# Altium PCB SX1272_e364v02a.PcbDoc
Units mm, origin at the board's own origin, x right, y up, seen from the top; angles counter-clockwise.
Board outline 65 x 53.3 mm, 4 copper layers (Top Layer, MidLayer1, MidLayer2, Bottom Layer), stack 1.661 mm thick; 73 components, 54 nets, 215 pads, 691 vias.
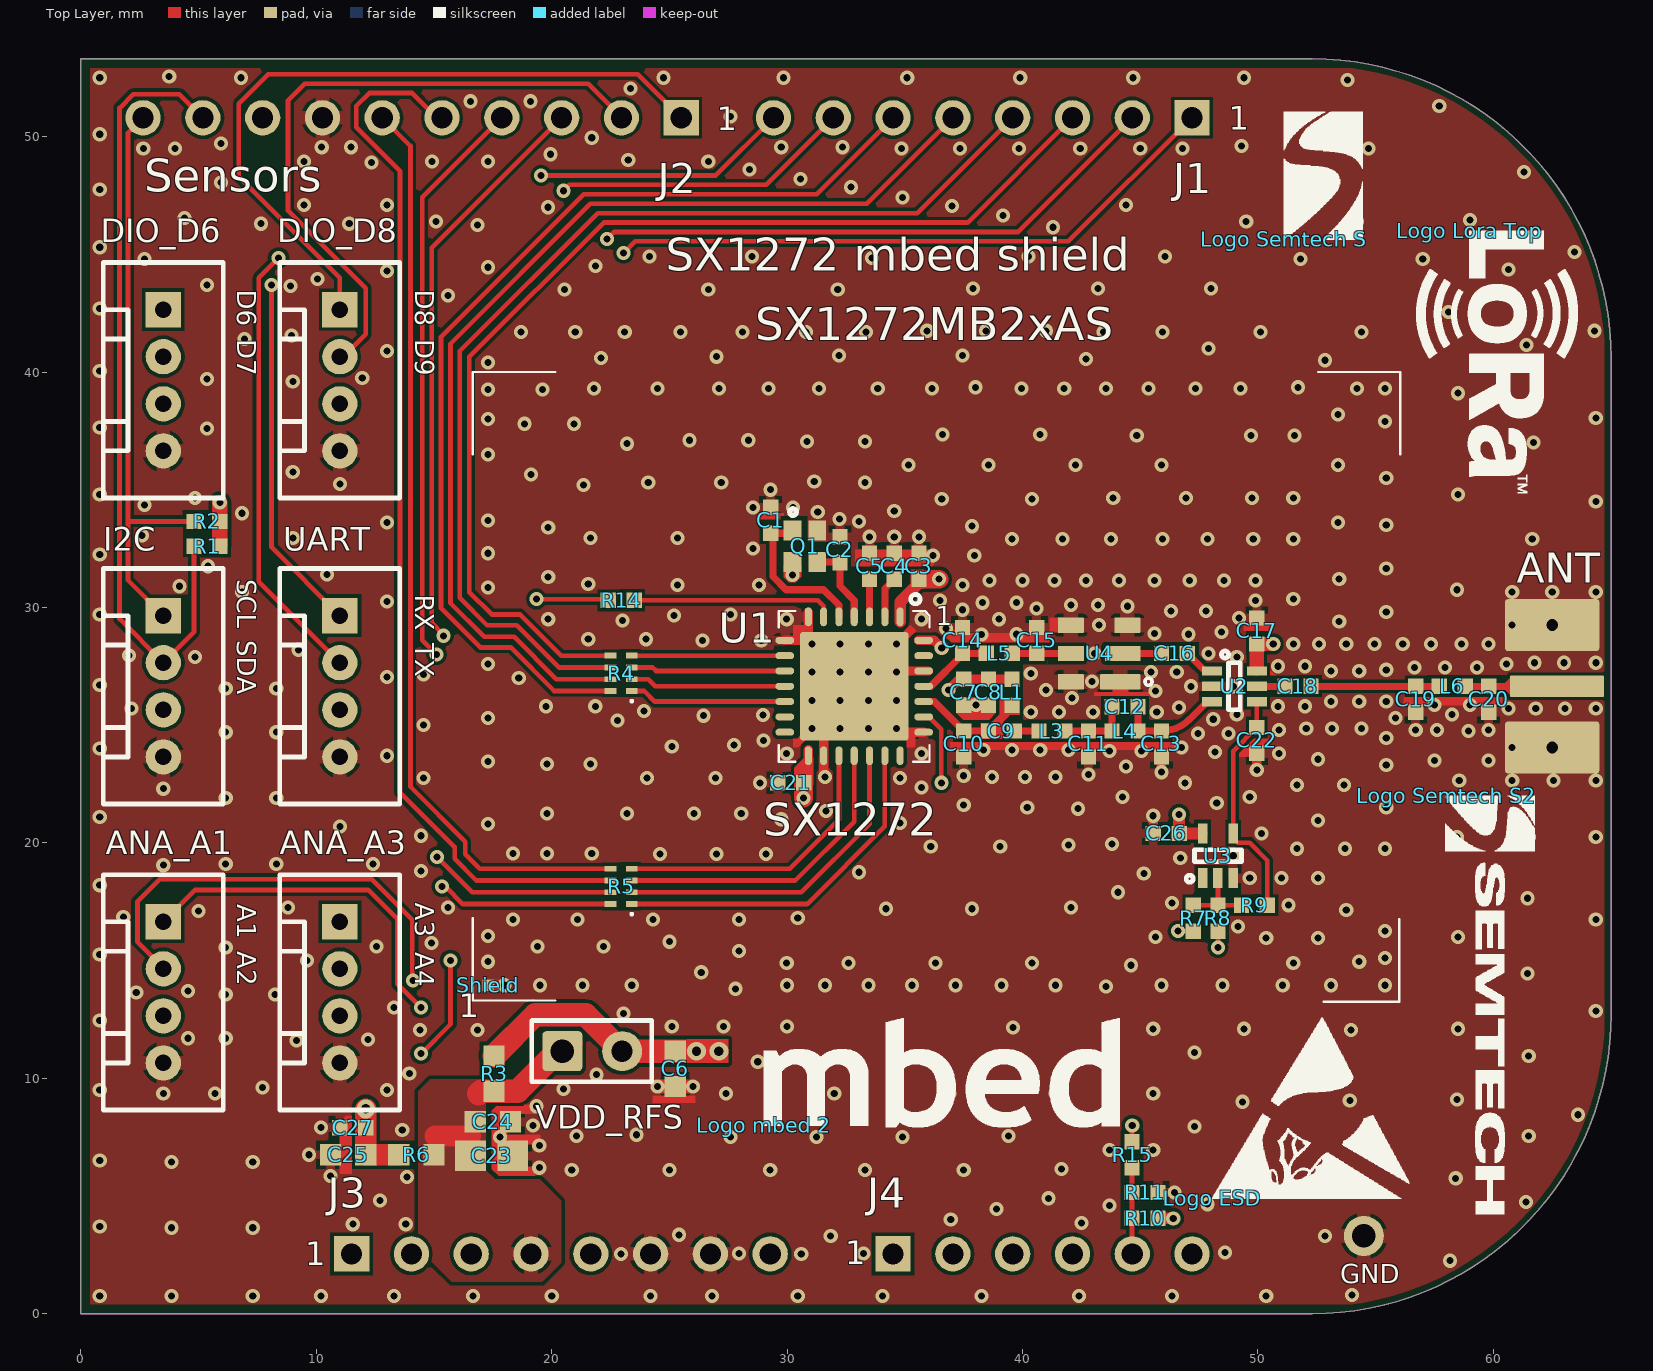
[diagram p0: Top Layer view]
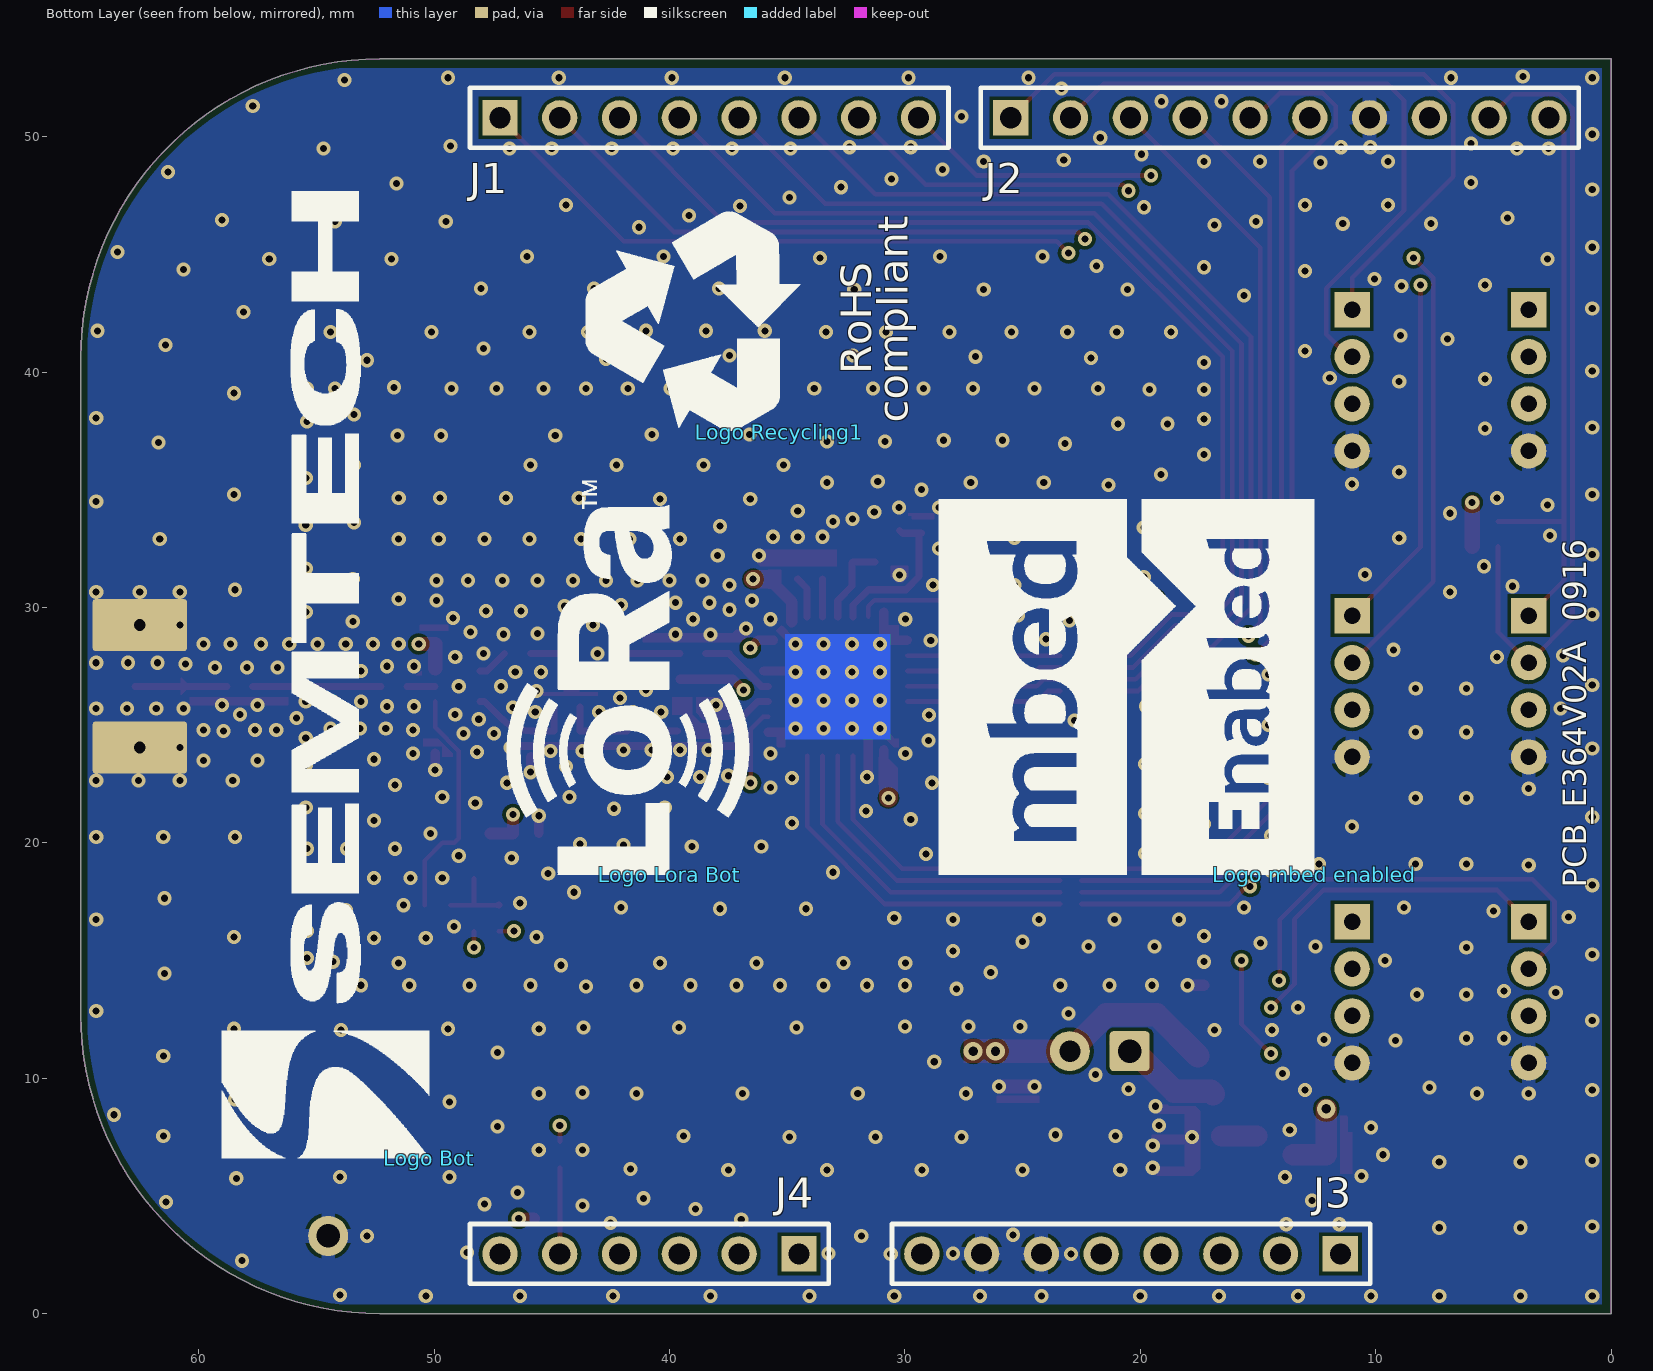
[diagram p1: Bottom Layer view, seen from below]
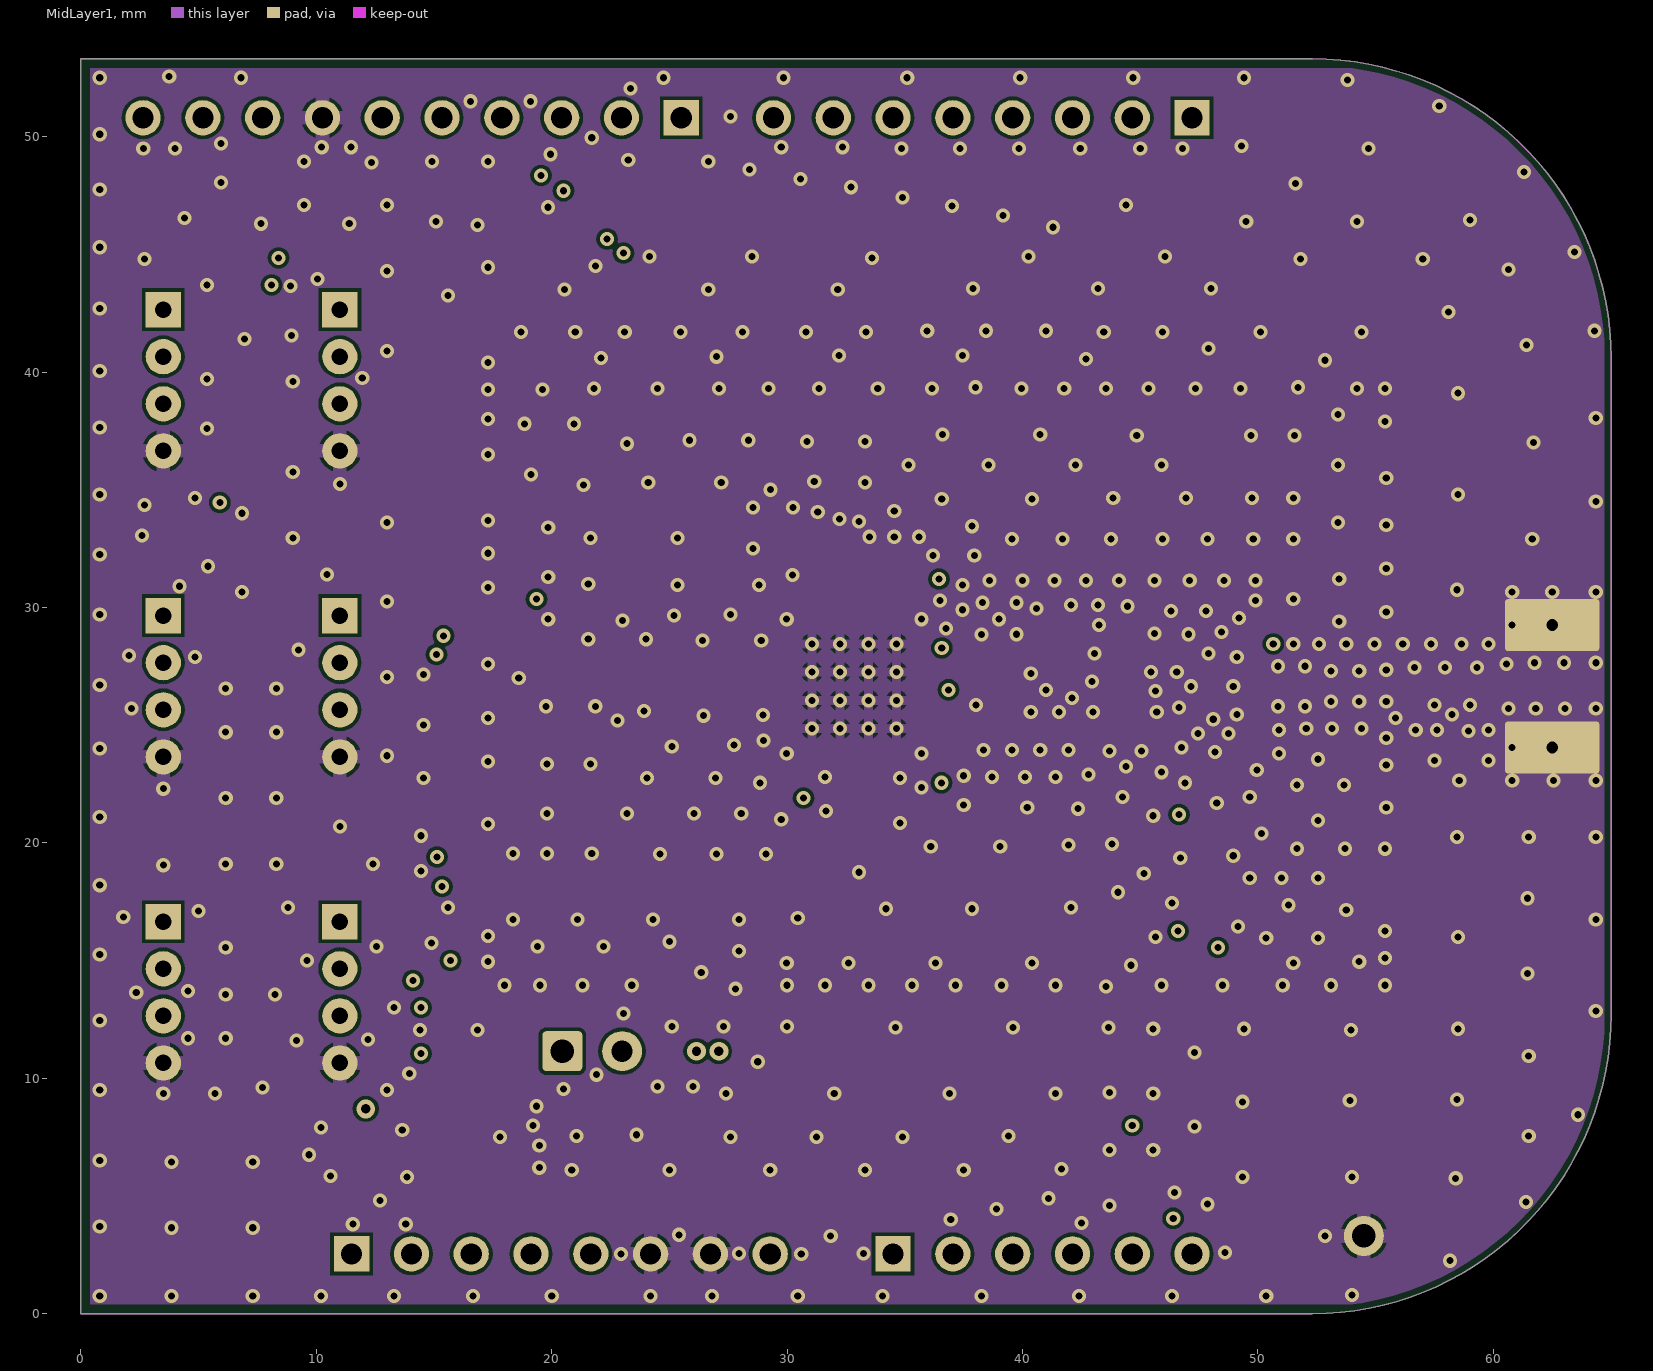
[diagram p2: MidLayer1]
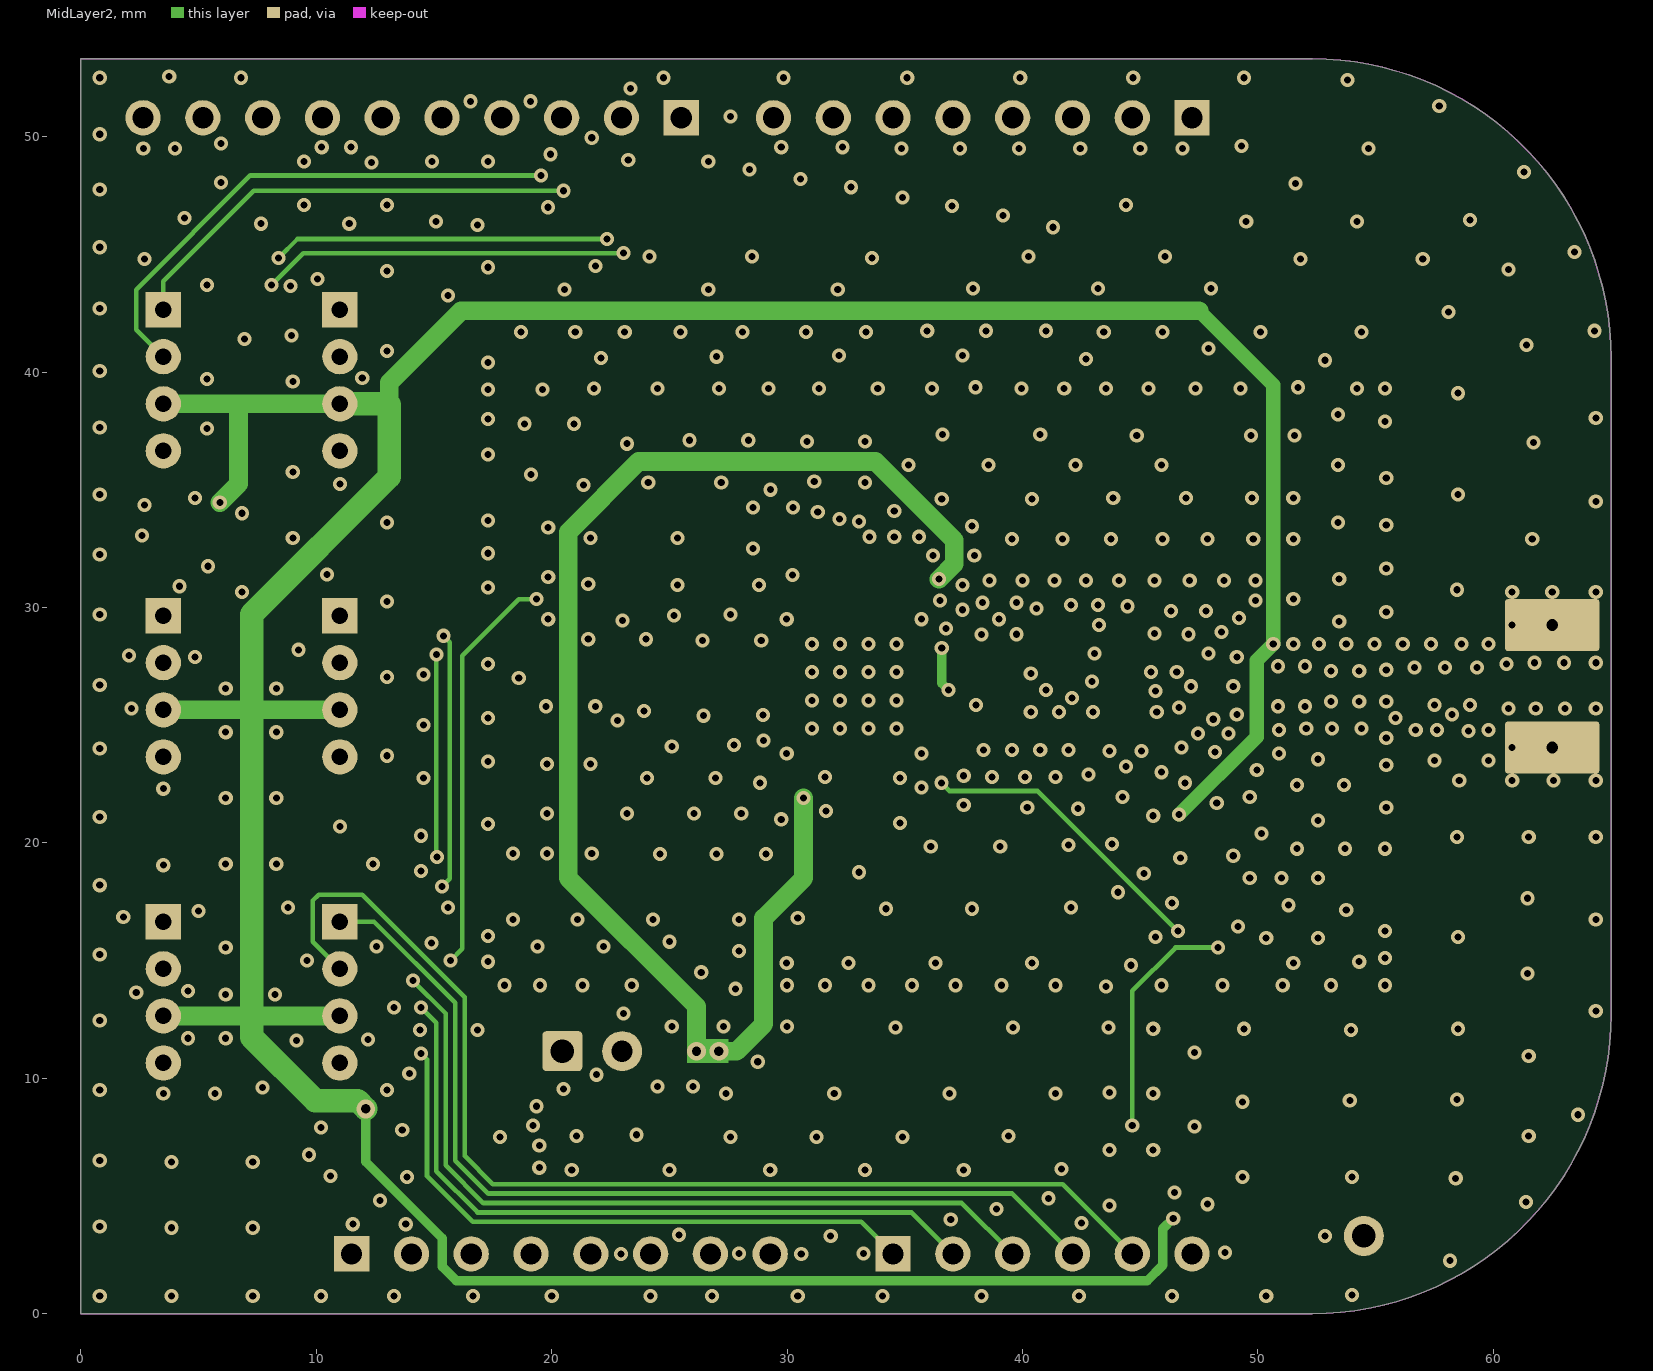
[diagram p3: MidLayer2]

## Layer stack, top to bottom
Top Layer: signal copper 0.035
Dielectric: core 0.2, FR-4, Dk 4.3
MidLayer1: signal copper 0.0356
Dielectric: prepreg 1.12, FR-4, Dk 4.3
MidLayer2: signal copper 0.0356
Dielectric: core 0.2, FR-4, Dk 4.3
Bottom Layer: signal copper 0.035

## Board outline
0,0 52.3,0 ccw(c52.3,12.7) 65,12.7 65,40.6 ccw(c52.3,40.6) 52.3,53.3 0,53.3

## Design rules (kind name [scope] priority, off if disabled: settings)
Clearance Clearance_GND_Keepout [InNet('GND') vs OnLayer('Keep-Out Layer')] p1: gap=0.25
Clearance Clearance_GND [InNet('GND')] p2: gap=0.15
Clearance [All] p3: gap=0.15
ComponentClearance [All] p1: gap=0.25 collisioncheckmode=3 verticalgap=0.3 showdistances=FALSE
HoleSize [All] p1: absolutevalues=TRUE maxlimit=3.6 minlimit=0.25 maxpercent=80.000 minpercent=20.000
HoleToHoleClearance [All] p1: gap=0.2 allowstackedmicrovias=TRUE
MinimumSolderMaskSliver [All] p1: minsoldermaskwidth=0.05
PlaneClearance [All] p1: clearance=0.2
PlaneConnect [All] p1: planeconnectstyle=Direct reliefexpansion=0.508 reliefentries=4 reliefconductorwidth=0.254 reliefairgap=0.254
PolygonConnect "PolygonConnect SAW SMD PACKAGE" [InNet('GND') vs HasFootprint('DCC6C_3.0X3.0MM')] p1: connectstyle=Relief reliefconductorwidth=0.65 reliefentries=4 polygonreliefangle="90 Angle"
PolygonConnect "PolygonConnect SMD" [InNet('GND') vs HasFootprint('vqfn28_6x6mm')  or HasFootprint('nd3225da - nd2520da')  or  HasFootprint('rlc_1206_smd capa pol') or HasFootprint('rlc_603_smd') or HasFootprint('rlc_402_smd') or HasFootprint('rlc_402_smd diode') or hasFootprint('rlc_805_smd') or HasFootprint('rlc_1210_smd')  or HasFootprint('SC70-6') or HasFootprint('SC70-5')] p2: connectstyle=Relief reliefconductorwidth=0.4 reliefentries=4 polygonreliefangle="90 Angle"
PolygonConnect PolygonConnect_comp_diverse [InNet('GND') or  InNet('VDD_RF') vs HasFootprint('CD1608-0603') or  HasFootprint('BRIDGE_254MM') or  HasFootprint('pin_1mm') or HasFootprint('SMA_END_LAUNCH_JACK_RECEPTACLE')   or  HasFootprint('HDR2X8')   or  HasFootprint('HDR2X6')  or  HasFootprint('HDR2X10')   or  HasFootprint('HDR1X10') or  HasFootprint('HDR1X8')  or  HasFootprint('HDR1X6')  or  HasFootprint('1125S-4P_connector')] p3: connectstyle=Relief reliefconductorwidth=0.6 reliefentries=4 polygonreliefangle="90 Angle"
PolygonConnect PolygonConnect_all [All] p4: connectstyle=Direct reliefconductorwidth=0.6 reliefentries=4 polygonreliefangle="90 Angle"
RoomDefinition SX1272_e364v02a [InComponentClass('SX1272_e364v02a')] p1: confinementstyle=ConfineOut formatcopy=TRUE lockcomponents=FALSE outline 94.9,15.9 94.9,42.5 95.1,42.7 139,42.7 139,16
RoutingVias [All] p1: holewidth=0.3 width=0.6 viastyle="Through Hole" minholewidth=0.25 minwidth=0.5 maxholewidth=0.4 maxwidth=0.8
SilkToSilkClearance [All] p1: silktosilkclearance=0.05
SilkscreenOverComponentPads [All] p1: minsilkscreentomaskgap=0.05
SolderMaskExpansion [All] p1: expansion=0.05
Width "Width GND" [InNet('GND')] p1: maxlimit=3 minlimit=0.2 preferedwidth=0.4
Width Width_VCC [InNet('VDD_RF') or  InNet('VDD_RFS') or  InNet('VCC') or  InNet('VBAT') or InNet('VCC_FEM')] p2: maxlimit=2 minlimit=0.2 preferedwidth=0.8
Width "Width All" [All] p3: maxlimit=2 minlimit=0.15 preferedwidth=0.2
20 further rules are at their usual default settings.

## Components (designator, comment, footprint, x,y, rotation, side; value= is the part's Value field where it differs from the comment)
ANA_A1 "Header 4" 1125S-4P_connector 3.5,16.65 r270 top locked
ANA_A3 "Header 4" 1125S-4P_connector 11,16.65 r270 top locked
ANT "SMA" "SMA END LAUNCH JACK RECEPTACLE SHORT" 62.7,26.65 r90 top locked
C1 "Cap" rlc_402_smd 29.3,33.7 r270 top
C2 "Cap" rlc_402_smd 32.245,32.45 r270 top
C3 "Cap" rlc_402_smd 35.6,31.75 r270 top
C4 "Cap" rlc_402_smd 34.55,31.75 r270 top
C5 "Cap" rlc_402_smd 33.5,31.75 r270 top
C6 "Cap" rlc_603_smd 25.25,10.4 r90 top
C7 "Cap" rlc_402_smd 37.5,26.4 r90 top
C8 "Cap" rlc_402_smd 38.55,26.4 r90 top
C9 "Cap" rlc_402_smd 39.1,24.75 r180 top
C10 "Cap" rlc_402_smd 37.5,24.2 r90 top
C11 "Cap" rlc_402_smd 42.8,24.2 r90 top
C12 "Cap" rlc_402_smd 44.35,25.777 r180 top
C13 "Cap" rlc_402_smd 45.9,24.2 r90 top
C14 "Cap" rlc_402_smd 37.45,28.6 r270 top
C15 "Cap" rlc_402_smd 40.6,28.6 r270 top
C16 "Cap" rlc_402_smd 46.45,28.046 r180 top
C17 "Cap" rlc_402_smd 49.95,29 r270 top
C18 "Cap" rlc_402_smd 51.7,26.65 r180 top
C19 "Cap" rlc_402_smd 56.7,26.1 r90 top
C20 "Cap" rlc_402_smd 59.8,26.1 r90 top
C21 "Cap" rlc_402_smd 30.15,22.55 r0 top
C22 "Cap" rlc_402_smd 49.95,24.35 r270 top
C23 "Cap" rlc_805_smd 17.45,6.7 r180 top
C24 "Cap" rlc_603_smd 17.5,8.15 r180 top
C25 "Cap" rlc_603_smd 11.35,6.75 r0 top
C26 "Cap" rlc_402_smd 46.1,20.4 r0 top
C27 "Cap" rlc_402_smd 11.55,7.9 r0 top
DIO_D6 "Header 4" 1125S-4P_connector 3.5,42.65 r270 top locked
DIO_D8 "Header 4" 1125S-4P_connector 11,42.65 r270 top locked
GND "Test Pin" pin_1mm 55,3.8 r0 top
I2C "Header 4" 1125S-4P_connector 3.5,29.65 r270 top locked
J1 "Header 8" HDR1X8 47.2,50.8 r180 bottom locked
J2 "Header 10" HDR1X10 25.5,50.8 r180 bottom locked
J3 "Header 8" HDR1X8 11.5,2.54 r0 bottom locked
J4 "Header 6" HDR1X6 34.5,2.54 r0 bottom locked
L1 "Inductor" rlc_402_smd 39.55,26.4 r90 top
L3 "Inductor" rlc_402_smd 41.25,24.75 r0 top
L4 "Inductor" rlc_402_smd 44.35,24.75 r0 top
L5 "Inductor" rlc_402_smd 39.01,28.05 r0 top
L6 "Inductor" rlc_402_smd 58.25,26.65 r0 top
"Logo Bot" "Logo symbol" logo_semtech_horiz_size4 50.2,6.6 r90 bottom
"Logo ESD" "Logo symbol" "Logo ESD" 48.05,4.9 r0 top
"Logo Lora Bot" "Logo symbol" "Logo LoRa Size4" 40,18.65 r90 bottom
"Logo Lora Top" "Logo symbol" "Logo LoRa Size3" 59,46 r270 top
"Logo mbed 2" "Logo symbol" "logo mbed 2" 29,8 r0 top
"Logo mbed enabled" "Logo symbol" "Logo mbed enabled 2" 12.6,18.65 r90 bottom
"Logo Recycling1" "Logo symbol" "Logo Recycling1" 35.334,37.45 r90 bottom
"Logo Semtech S" "Logo symbol" Logo_Semtech_S_2 51.1,45.65 r0 top
"Logo Semtech S2" "Logo symbol" logo_semtech_horiz_size2 58,22 r270 top
Q1 "Xtal" ND2016DA 30.75,32.6 r270 top
R1 "Resistor" rlc_402_smd 5.35,32.6 r0 top
R2 "Resistor" rlc_402_smd 5.35,33.65 r0 top
R3 "Resistor" rlc_603_smd 17.55,10.2 r270 top
R4 "EXBN8VxxxJX" EXB28V 22.95,27.2 r90 top
R5 "EXBN8VxxxJX" EXB28V 22.95,18.15 r90 top
R6 "Resistor" rlc_603_smd 14.25,6.75 r0 top
R7 "Resistor" rlc_402_smd 47.25,16.8 r270 top
R8 "Resistor" rlc_402_smd 48.3,16.8 r270 top
R9 "Resistor" rlc_402_smd 49.85,17.35 r180 top
R10 "Resistor" rlc_402_smd 45.2,4.05 r180 top
R11 "Resistor" rlc_402_smd 45.2,5.15 r0 top
R14 "Resistor" rlc_402_smd 22.95,30.3 r180 top
R15 "Resistor" rlc_402_smd 44.65,6.75 r270 top
Shield "Logo symbol" "BMIS-205-F - SHIELD" 17.3,13.95 r0 top locked
U1 "SX1272" vqfn28_6x6mm 32.85,26.65 r270 top locked
U2 "RF Switch" SC70-6 49,26.65 r0 top
U3 "NC7SZ04" SC70-5 48.3,19.45 r90 top
U4 "SAW Filter" DCC6C_3.0X3.0MM 43.25,28.046 r180 top
UART "Header 4" 1125S-4P_connector 11,29.65 r270 top locked
VDD_RFS "Jumper" BRIDGE_254MM 20.45,11.15 r0 top locked

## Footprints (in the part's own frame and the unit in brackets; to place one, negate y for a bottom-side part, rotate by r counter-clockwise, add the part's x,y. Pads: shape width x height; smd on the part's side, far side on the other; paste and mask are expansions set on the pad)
1125S-4P_connector [mm] "Connector; Header; 4 Position; P/N: 1125S-4P; Manuf: TAIFENG"
  rect 1.5x1.5 hole 0.7 mask+0.05: 1(0,0)
  round 1.5 hole 0.7 mask+0.05: 2(2,0) 3(4,0) 4(6,0)
  silkscreen extent -2,-2.55 8,2.55, body extent -2,-2.55 8,2.55, height 2.95
"BMIS-205-F - SHIELD" [mm] "BMIS-205-F EMI Gasket - modif SolderMask - Standard Surface Mount Shields -  Laird Technologies"
  rect 0.5x0.5 smd paste-1 mask+0.05: 1(0,0)
  Mechanical 15 keep-out lines w1: 0,0 38.1,0 38.1,25.4 0,25.4 0,0
  silkscreen extent -0.65,-0.7 38.75,26.05, body extent -0.65,-0.65 2.85,2.85, height 6.5
BRIDGE_254MM [mm] "Generic Bridge 2.54mm, 2 Leads 0.9mm;"
  rrect20% 1.7x1.7 hole 1 paste+0 mask+0.05: 1(0,0)
  round 1.7 hole 0.9 paste+0 mask+0.05: 2(2.54,0)
  silkscreen extent -1.3,-1.3 3.8,1.3, body extent -1.4,-1.4 3.9,1.4, height 1
DCC6C_3.0X3.0MM [mm] "DCC6C footprint, 3.0x3.0mm"
  rrect5% 1.7x0.65 smd mask+0.05: 1(-0.9,1.2)
  rrect5% 1.5x0.65 smd mask+0.05: 2(-1,0)
  rrect5% 1.1x0.65 smd mask+0.05: 3(-1.2,-1.2) 4(1.2,-1.2) 5(1.2,0) 6(1.2,1.2)
  silkscreen extent -2.25,1.05 -1.95,1.35, body extent -1.5,-1.5 1.5,1.5, height 1
EXB28V [mm] "Chip Resistor Array, (0402x4); SM; 8 Leads; Body 2.10 x 1.10 mm (LxW max)"
  rect 0.25x0.5 smd: 1(-0.75,-0.45) 2(-0.25,-0.45) 3(0.25,-0.45) 4(0.75,-0.45) 5(0.75,0.45) 6(0.25,0.45) 7(-0.25,0.45) 8(-0.75,0.45)
  silkscreen extent -1.23,-0.5 -1.13,-0.4
HDR1X6 [mm] "Connector; Header; 6 Position"
  rect 1.5x1.5 hole 0.9: 1(0,0)
  round 1.5 hole 0.9: 2(2.54,0) 3(5.08,0) 4(7.62,0) 5(10.16,0) 6(12.7,0)
  silkscreen extent -1.27,-1.27 13.97,1.27
HDR1X8 [mm] "Connector; Header; 8 Position"
  rect 1.5x1.5 hole 0.9: 1(0,0)
  round 1.5 hole 0.9: 2(2.54,0) 3(5.08,0) 4(7.62,0) 5(10.16,0) 6(12.7,0) 7(15.24,0) 8(17.78,0)
  silkscreen extent -1.27,-1.27 19.05,1.27
HDR1X10 [mm] "Connector; Header; 10 Position"
  rect 1.5x1.5 hole 0.9: 1(0,0)
  round 1.5 hole 0.9: 2(2.54,0) 3(5.08,0) 4(7.62,0) 5(10.16,0) 6(12.7,0) 7(15.24,0) 8(17.78,0) 9(20.32,0) 10(22.86,0)
  silkscreen extent -1.27,-1.27 24.13,1.27
"Logo ESD" [mm] "Logo ESD"
  silkscreen extent 0,0 8.38,7.67
"Logo LoRa Size3" [mm] "Logo LoRa Size3 - Top Overlay"
  silkscreen extent 0,-2.26 11.16,4.59
"Logo LoRa Size4" [mm] "Logo LoRa Size4 - Top Overlay"
  silkscreen extent 0,-3.38 16.73,6.89
"logo mbed 2" [mm] "logo mbed 2"
  silkscreen extent 0,-0.06 15.12,4.54
"Logo mbed enabled 2" [mm] "Logo mbed enabled 2"
  silkscreen extent 0,0 15.95,15.93
"Logo Recycling1" [mm] "Logo Recycling1"
  silkscreen extent 0.05,-0.88 9.36,8.2
logo_semtech_horiz_size2 [mm] "Logo semtech horizontal - size2 - M"
  silkscreen extent 0,-0.03 17.78,3.76
logo_semtech_horiz_size4 [mm] "Logo semtech horizontal - size4 - XL"
  silkscreen extent 0,0 41.07,8.79
Logo_Semtech_S_2 [mm] "Logo semtech S - size2"
  silkscreen extent 0,0 3.35,5.41
ND2016DA [mm] "Crystal SMD 2.0x1.6mm"
  rect 0.85x0.75 smd mask+0.05: 1(-0.675,-0.525) 2(0.675,-0.525) 3(0.675,0.525) 4(-0.675,0.525)
  silkscreen extent -1.6,-0.65 -1.3,-0.35, body extent -1,-0.8 1,0.8, height 1
pin_1mm [mm] "Generic Pin 1.1mm; 1 Lead"
  round 1.7 hole 1 paste+0 mask+0.05: 1(-0.5,-0.5)
rlc_402_smd [mm] "Chip SMD component 402; Body 1.0 x 0.5 mm (LxW typ)"
  rect 0.65x0.65 smd mask+0.05: 1(-0.55,0) 2(0.55,0)
rlc_603_smd [mm] "Chip SMD component 603; Body 1.6 x 0.8mm (LxW typ)"
  rect 0.9x0.9 smd paste+0 mask+0.05: 1(-0.75,0) 2(0.75,0)
rlc_805_smd [mm] "Chip SMD component 805; Body 2.0 x 1.25 mm (LxW typ)"
  rect 1.3x1.3 smd mask+0.05: 1(-0.9,0) 2(0.9,0)
SC70-5 [mm] "SC70 5-Leads, Body 2.0x1.25mm, Pitch 0.65mm"
  rect 0.85x0.4 smd mask+0.05: 1(-0.95,0.65) 2(-0.95,0) 3(-0.95,-0.65) 4(0.95,-0.65) 5(0.95,0.65)
  silkscreen extent -1.12,-1 0.25,1.35, body extent -0.63,-1 0.63,1, height 1.45
SC70-6 [mm] "SC70 6-Leads, Body 2.0x1.25mm, Pitch 0.65mm"
  rect 0.85x0.4 smd mask+0.05: 1(-0.95,0.65) 2(-0.95,0) 3(-0.95,-0.65) 4(0.95,-0.65) 5(0.95,0) 6(0.95,0.65)
  silkscreen extent -0.55,-1 0.25,1.5, body extent -0.63,-1 0.63,1, height 1.45
"SMA END LAUNCH JACK RECEPTACLE SHORT" [mm] "SMA Connector - End Launch Jack Receptacle - Short"
  rrect10% 0.9x4 smd paste+0 mask+0.05: 1(0,0)
  rrect10% 2.2x4 hole 0.5 mask+0.05: 2(-2.6,0.2) 2(2.6,0.2)
vqfn28_6x6mm [mm] "28 Leads, Body 6.0x6.0mm, Pitch 0.65mm, VQFN28"
  oval 0.8x0.3 smd mask+0.05: 1(-2.95,1.95) 2(-2.95,1.3) 3(-2.95,0.65) 4(-2.95,0) 5(-2.95,-0.65) 6(-2.95,-1.3) 7(-2.95,-1.95) 15(2.95,-1.95) 16(2.95,-1.3) 17(2.95,-0.65) 18(2.95,0) 19(2.95,0.65) 20(2.95,1.3) 21(2.95,1.95)
  oval 0.3x0.8 smd mask+0.05: 8(-1.95,-2.95) 9(-1.3,-2.95) 10(-0.65,-2.95) 11(0,-2.95) 12(0.65,-2.95) 13(1.3,-2.95) 14(1.95,-2.95) 22(1.95,2.95) 23(1.3,2.95) 24(0.65,2.95) 25(0,2.95) 26(-0.65,2.95) 27(-1.3,2.95) 28(-1.95,2.95)
  rrect5% 4.6x4.6 smd paste-3.3 mask+0.05: 29(0,0)
  Mechanical 15 keep-out lines w0.1: 3.5,-3.5 -3.5,-3.5 -3.5,3.5 3.5,3.5 3.5,-3.5
  silkscreen extent -3.9,-3.2 3.2,3.2, body extent -3,-3 3,3, height 1

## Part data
ANA_A1 ANA_A3 DIO_D6 DIO_D8 I2C UART: "Header, 4-Pin"
ANT: "SMA Straight Connector"
C1 C2 C3 C4 C5 C6 C7 C8 C9 C10 C11 C12 C13 C14 C15 C16 C17 C18 C19 C20 C21 C22 C23 C24 C25 C26 C27: "Capacitor SMD"
GND: library part test_pin
J1 J3: "Header, 8-Pin"
J2: "Header, 10-Pin"
J4: "Header, 6-Pin"
L1 L3 L4 L5 L6: "Inductor SMD"
"Logo Bot" "Logo ESD" "Logo Lora Bot" "Logo Lora Top" "Logo mbed 2" "Logo mbed enabled" "Logo Recycling1" "Logo Semtech S" "Logo Semtech S2": library part Logo, "Schematic symbol for Logo"
Q1: library part xtal_gnd, "Crystal with GND pins"
R1 R2 R3 R6 R7 R8 R9 R10 R11 R14 R15: "Resistor SMD - IEC symbol version"
R4 R5: "Mini-Flat Package, Isolated Resistor Network, 0.031 W/resistor"
Shield: library part Shield, "Shield - EMI Gasket - Standard Surface Mount Shields"
U1: "SX1272 - Low Power Integrated UHF Transceiver with Lora technology"
U2: library part "PE4259 RF Switch", "PE4259 Peregrine RF Switch"
U3: "NC7SZ04 - TinyLogic HS Single Inverter - Fairchild Semi"
U4: "SAW Filter - Bandpass - TEMEX type"
VDD_RFS: "Jumper Wire"

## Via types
v1: diameter 0.6, hole 0.3, Top Layer to Bottom Layer, tented both sides, 672 vias
v2: diameter 0.6, hole 0.3, Top Layer to Bottom Layer, tented top, 16 vias
v3: diameter 0.8, hole 0.4, Top Layer to Bottom Layer, tented both sides, 3 vias

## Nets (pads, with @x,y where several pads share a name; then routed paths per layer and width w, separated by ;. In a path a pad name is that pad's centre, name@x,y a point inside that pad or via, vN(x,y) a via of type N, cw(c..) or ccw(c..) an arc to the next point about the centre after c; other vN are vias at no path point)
AD1: ANA_A1.1 J4.2 | length 45.8
  Top Layer w0.2: ANA_A1.1 4.85,18 12.198,18 13.45,16.748 13.45,14 v1(14.45,13)
  MidLayer2 w0.2: v1(14.45,13) 15.1,12.35 15.1,6.05 16.85,4.3 35.28,4.3 J4.2
AD2: ANA_A1.2 J4.3 | length 52.7
  Top Layer w0.2: ANA_A1.2 3.5,14.7 2.4,15.8 2.4,17.5 3.35,18.45 12.345,18.45 14.072,16.723 14.072,14.178 v1(14.1,14.15)
  MidLayer2 w0.2: v1(14.1,14.15) 15.5,12.75 15.5,6.3 17.1,4.7 37.42,4.7 J4.3
AD3: ANA_A3.1 J4.4 | length 40.9
  MidLayer2 w0.2: ANA_A3.1 12.45,16.65 15.9,13.2 15.9,6.5 17.3,5.1 39.56,5.1 J4.4
AD4: ANA_A3.2 J4.5 R10.2 R11.1 R15.2 | length 52.2
  Top Layer w0.2: R15.2 R11.1 R10.2 44.65,2.55 J4.5
  MidLayer2 w0.2: ANA_A3.2 9.85,15.8 9.85,17.55 10.1,17.8 11.95,17.8 16.3,13.45 16.3,6.7 17.5,5.5 41.7,5.5 J4.5
D6: DIO_D6.1 J1.7 | length 32.5
  Top Layer w0.2: v1(20.5,47.7) 20.75,47.95 29.11,47.95 J1.7
  MidLayer2 w0.2: DIO_D6.1 3.5,43.85 7.35,47.7 v1(20.5,47.7)
D7: DIO_D6.2 J1.8 | length 33.4
  Top Layer w0.2: v1(19.55,48.35) 26.97,48.35 J1.8
  MidLayer2 w0.2: DIO_D6.2 2.35,41.8 2.35,43.5 7.2,48.35 v1(19.55,48.35)
D8: DIO_D8.1 J2.1 | length 30.6
  Top Layer w0.2: DIO_D8.1 11,44 6.7,48.3 6.7,51.4 7.95,52.65 23.644,52.65 25.494,50.8 J2.1
D9: DIO_D8.2 J2.2 | length 27.9
  Top Layer w0.2: DIO_D8.2 11.15,40.65 12.1,41.6 12.1,43.55 8.8,46.85 8.8,51.55 9.5,52.25 21.55,52.25 22.96,50.84 J2.2
DIO0: J1.3 R4.5 | length 46.9
  Top Layer w0.2: R4.5 20.4,27.95 18.65,29.7 17.447,29.7 16.5,30.647 16.5,40.64 22.21,46.35 37.67,46.35 J1.3
DIO0_SX: R4.4 U1.9 | length 6.5
  Top Layer w0.2: R4.4 U1.9
DIO1: J1.4 R4.6 | length 45.7
  Top Layer w0.2: R4.6 20.3,27.45 18.504,29.246 17.251,29.246 16.092,30.405 16.092,40.892 21.95,46.75 35.53,46.75 J1.4
DIO1_SX: R4.3 U1.10 | length 6.6
  Top Layer w0.2: R4.3 24.28,27.45 24.43,27.3 U1.10
DIO2: J1.5 R4.7 | length 44.5
  Top Layer w0.2: R4.7 20.2,26.95 18.4,28.75 17.13,28.75 15.7,30.18 15.7,41.205 21.645,47.15 33.39,47.15 J1.5
DIO2_SX: R4.2 U1.11 | length 6.6
  Top Layer w0.2: R4.2 24.1,26.95 24.4,26.65 U1.11
DIO3: J1.6 R4.8 | length 43.2
  Top Layer w0.2: R4.8 20.1,26.45 18.25,28.3 16.959,28.3 15.3,29.959 15.3,41.492 21.358,47.55 31.25,47.55 J1.6
DIO3_SX: R4.1 U1.12 | length 6.7
  Top Layer w0.2: R4.1 23.93,26.45 24.38,26 U1.12
GND: ANA_A1.4 ANA_A3.4 ANT.2 C1.1 C2.1 C3.1 C4.1 C5.1 C6.1 C7.1 C8.1 C10.1 C11.1 C13.1 C14.1 C15.1 C17.1 C19.1 C20.1 C21.1 C22.2 C23.1 C24.1 C25.1 C26.1 C27.1 DIO_D6.4 DIO_D8.4 GND.1 I2C.4 J2.7 J3.6 J3.7 Q1.2 Q1.4 R11.2 Shield.1 U1.7 U1.8 U1.16 U1.22 U1.26 U1.29 U2.2 U3.3 U4.1 U4.3 U4.4 U4.6 UART.4 | length 20
  Top Layer w0.3: U1.29 U1.29@32.85,26.672 ; U1.29@32.86,26.65 U1.29@33.455,27.245
  Top Layer w0.4: U1.8 U1.29@30.9,28.6 ; U1.7@30.9,29.8 U1.7 U1.29@30.9,28.6 ; U1.29@31.55,25.35 U1.16 31.55,22.85 v1(31.6,22.8) ; U1.29 v2(32.25,27.25) v2(31.05,28.45) U1.29@30.9,28.6 ; U1.29@33.51,27.3 U1.26 U1.26@35.992,27.3 ; U1.29@34.8,24.7 U1.22 ; C7.1 v1(38.025,25.85) C8.1 ; C26.1 v1(45.55,21.15) ; v1(45.9,23) C13.1 ; v1(49.95,23.1) C22.2
  Top Layer w0.5: Shield.1 v1(18,13.95) ; U1.29 v2(33.45,26.05) v2(34.65,24.85) U1.29@34.8,24.7
  Top Layer w0.6: v1(24.5,9.65) C6.1 v1(26,9.65)
  other v1: 0.8,0.75 3.85,0.75 7.3,0.75 10.2,0.75 13.3,0.75 16.65,0.75 20,0.75 24.2,0.75 26.8,0.75 30.45,0.75 34.05,0.75 38.25,0.75 42.4,0.75 46.35,0.75 50.35,0.75 54,0.8 58.15,2.25 22.95,2.54 27.95,2.55 30.6,2.54 33.25,2.55 48.6,2.6 31.85,3.3 52.85,3.3 25.4,3.35 3.85,3.65 7.3,3.65 0.8,3.7 11.55,3.8 13.8,3.8 42.5,3.85 36.95,4 38.9,4.45 43.7,4.6 47.85,4.65 61.383,4.75 12.7,4.8 41.1,4.9 46.45,5.15 58.4,5.75 13.85,5.8 49.35,5.8 54,5.8 10.6,5.841 20.85,6.1 25,6.1 29.28,6.1 33.3,6.1 37.5,6.1 41.65,6.15 19.472,6.2 3.85,6.45 7.3,6.45 0.8,6.5 9.691,6.75 43.7,6.95 45.55,6.95 19.472,7.15 17.8,7.5 27.6,7.5 31.25,7.5 34.9,7.5 21.05,7.55 39.403,7.55 61.5,7.55 23.6,7.6 13.65,7.8 10.2,7.9 47.3,7.95 19.2,8 63.602,8.45 19.35,8.809 49.35,9 53.9,9.05 58.45,9.1 3.5,9.35 5.7,9.35 27.4,9.35 32,9.35 36.9,9.35 41.4,9.35 45.55,9.35 43.7,9.4 0.8,9.5 13,9.5 20.5,9.55 7.72,9.6 21.9,10.15 13.95,10.2 28.75,10.7 61.5,10.95 47.3,11.1 9.15,11.6 12.2,11.65 4.55,11.7 6.15,11.7 14.4,12.05 16.85,12.05 53.95,12.05 45.55,12.1 49.4,12.1 58.5,12.1 34.6,12.15 39.6,12.15 43.65,12.15 25.1,12.2 27.3,12.2 30,12.2 0.8,12.45 23.05,12.75 64.35,12.85 13.3,13 6.15,13.55 8.25,13.55 2.35,13.65 4.55,13.7 27.8,13.8 43.55,13.9 19.5,13.95 21.3,13.95 23.4,13.95 30,13.95 31.6,13.95 33.45,13.95 35.3,13.95 37.15,13.95 39.1,13.95 41.4,13.95 45.9,13.95 48.5,13.95 51.05,13.95 53.1,13.95 55.402,13.95 61.45,14.45 26.35,14.5 44.6,14.8 29.982,14.9 32.6,14.9 36.3,14.9 40.4,14.9 51.5,14.9 17.3,14.95 54.3,14.95 9.6,15 55.402,15.1 0.8,15.25 27.95,15.4 6.15,15.55 12.55,15.6 19.4,15.6 22.2,15.6 14.9,15.75 25,15.8 50.35,15.95 52.55,15.95 45.65,16 58.5,16 17.3,16.05 55.402,16.25 49.15,16.45 18.35,16.75 21.1,16.75 24.3,16.75 27.95,16.75 64.35,16.75 30.45,16.8 1.8,16.85 5,17.1 53.75,17.15 34.2,17.2 37.85,17.2 8.8,17.25 15.6,17.25 42.05,17.25 51.3,17.35 46.35,17.45 61.45,17.645 44.05,17.9 0.8,18.2 49.65,18.5 51,18.5 52.55,18.5 45.15,18.7 33.05,18.75 14.45,18.8 3.5,19.05 6.15,19.1 8.3,19.1 12.4,19.1 46.7,19.35 48.95,19.45 18.35,19.55 19.8,19.55 21.7,19.55 24.6,19.526 27,19.526 29.1,19.526 51.65,19.75 53.7,19.75 55.402,19.75 36.1,19.85 39.05,19.85 41.95,19.9 43.8,19.95 58.45,20.25 61.5,20.25 64.35,20.25 14.45,20.3 50.15,20.4 11,20.7 17.294,20.8 34.8,20.85 52.55,20.95 29.75,21 0.8,21.1 19.8,21.25 23.2,21.25 26.05,21.25 28.05,21.25 31.65,21.35 42.35,21.45 40.2,21.5 55.45,21.5 37.5,21.6 48.25,21.7 6.15,21.9 8.3,21.9 44.25,21.95 49.65,21.95 3.5,22.3 35.7,22.35 51.65,22.45 53.65,22.45 28.85,22.55 46.9,22.55 58.55,22.65 60.8,22.65 62.55,22.65 64.35,22.65 14.55,22.75 24.05,22.75 26.95,22.75 34.8,22.75 38.7,22.8 40.1,22.8 41.4,22.8 37.5,22.85 42.8,22.9 44.4,23.25 55.45,23.3 19.8,23.35 21.65,23.35 17.286,23.45 57.5,23.5 59.8,23.5 52.55,23.55 13,23.7 29.982,23.79 35.7,23.8 50.9,23.8 48.183,23.855 43.7,23.9 45.05,23.9 38.34,23.95 39.55,23.95 40.75,23.95 41.95,23.95 0.8,24 46.75,24.05 60.8,24.05 25.1,24.1 27.75,24.15 29,24.355 55.45,24.45 47.45,24.65 48.75,24.65 6.15,24.7 8.3,24.7 58.95,24.75 50.9,24.8 56.7,24.8 57.6,24.8 59.8,24.8 52.05,24.85 53.15,24.85 54.4,24.85 14.55,25 22.8,25.2 48.1,25.25 17.286,25.3 55.85,25.3 26.44,25.4 28.98,25.428 49.1,25.45 58.25,25.45 40.35,25.55 41.55,25.55 43,25.55 45.7,25.55 23.925,25.6 2.15,25.7 60.65,25.7 61.8,25.7 63.05,25.7 64.35,25.7 46.65,25.75 19.75,25.8 21.85,25.8 50.85,25.8 52,25.8 57.5,25.85 59,25.85 53.1,26 54.3,26 55.45,26 42.1,26.15 45.65,26.45 41,26.5 6.15,26.55 8.3,26.55 47.15,26.65 48.95,26.65 0.8,26.7 42.95,26.85 18.6,27 13,27.05 14.55,27.15 40.35,27.2 45.45,27.25 46.55,27.25 53.1,27.3 54.3,27.3 55.45,27.35 56.65,27.45 57.95,27.45 59.3,27.45 50.85,27.5 52,27.5 17.3,27.6 60.55,27.6 61.75,27.65 63,27.65 64.35,27.65 4.85,27.9 49.1,27.9 2.05,27.95 43.05,28.05 47.9,28.05 9.25,28.2 51.5,28.45 52.6,28.45 53.75,28.45 54.95,28.45 56.15,28.45 57.35,28.45 58.65,28.45 59.8,28.45 26.4,28.6 28.9,28.6 21.55,28.65 24,28.65 38.25,28.85 39.75,28.86 47.05,28.86 45.6,28.9 48.45,28.95 36.75,29.1 43.25,29.25 60.8,29.25 53.45,29.4 23,29.45 19.85,29.5 29.982,29.5 35.7,29.5 39,29.5 49.2,29.55 25.2,29.65 0.8,29.7 27.6,29.7 55.45,29.8 46.3,29.85 47.8,29.85 37.45,29.9 40.6,29.95 44.45,30.05 42.05,30.1 43.2,30.1 38.3,30.2 39.75,30.2 13,30.25 36.5,30.3 49.9,30.3 51.5,30.35 6.85,30.65 60.8,30.65 62.5,30.65 64.35,30.65 58.45,30.75 17.3,30.85 4.18,30.9 25.35,30.95 28.8,30.95 37.45,30.95 21.55,31 38.6,31.15 40,31.15 41.35,31.15 42.7,31.15 44.1,31.15 45.6,31.15 47.1,31.15 48.55,31.15 49.9,31.15 53.45,31.2 19.85,31.3 30.22,31.37 10.45,31.4 55.45,31.65 5.4,31.75 36.2,32.2 37.95,32.2 0.8,32.25 17.3,32.3 28.55,32.5 39.55,32.9 41.7,32.9 43.75,32.9 45.95,32.9 47.85,32.9 49.8,32.9 51.5,32.9 61.65,32.9 9,32.95 21.65,32.95 25.35,32.95 33.5,33 34.55,33 35.6,33 2.596,33.05 19.85,33.4 37.85,33.45 55.45,33.5 13,33.6 53.4,33.6 33.05,33.65 17.3,33.7 32.22,33.75 6.85,34 31.3,34.05 34.55,34.1 28.55,34.25 30.25,34.25 2.7,34.35 64.35,34.5 36.568,34.6 40.4,34.6 4.85,34.65 43.85,34.65 46.95,34.65 49.75,34.65 51.5,34.65 0.8,34.8 58.5,34.8 29.3,35 21.35,35.2 11,35.25 24.1,35.3 27.2,35.3 33.3,35.3 31.15,35.35 55.45,35.5 19.12,35.65 9,35.75 35.15,36.05 38.55,36.05 42.25,36.05 45.9,36.05 53.4,36.05 17.3,36.491 23.2,36.955 61.7,37 30.85,37.05 33.3,37.05 25.85,37.1 28.35,37.1 44.85,37.3 49.7,37.3 51.55,37.3 36.6,37.35 40.75,37.35 5.35,37.6 0.8,37.65 18.85,37.8 20.95,37.8 55.4,37.9 17.3,38 64.35,38.05 53.4,38.2 58.5,39.1 17.294,39.25 19.6,39.25 21.8,39.3 24.5,39.3 27.1,39.3 29.2,39.3 31.35,39.3 33.85,39.3 36.15,39.3 39.95,39.3 41.769,39.3 43.55,39.3 45.35,39.3 47.35,39.3 49.25,39.3 54.2,39.3 55.4,39.3 38,39.35 51.7,39.35 9,39.6 5.35,39.7 11.95,39.75 0.8,40.05 17.286,40.4 52.85,40.5 42.7,40.55 22.1,40.6 27,40.65 32.2,40.7 37.45,40.7 13,40.892 47.9,41 61.4,41.15 6.95,41.4 8.95,41.55 18.7,41.7 21,41.7 23.1,41.7 25.476,41.7 28.1,41.7 30.8,41.7 33.35,41.7 43.45,41.7 45.95,41.7 50.1,41.7 54.4,41.7 35.95,41.75 38.45,41.75 41,41.75 64.3,41.75 58.1,42.55 0.8,42.7 15.6,43.25 20.55,43.5 26.65,43.5 32.15,43.5 37.9,43.55 43.2,43.55 48,43.55 8.9,43.65 5.35,43.7 10.05,43.95 13,44.293 60.65,44.35 17.286,44.45 21.856,44.5 2.7,44.8 51.8,44.8 57,44.8 33.6,44.85 24.15,44.9 28.5,44.9 40.25,44.9 46.05,44.9 63.45,45.1 0.8,45.3 41.3,46.15 16.85,46.25 7.65,46.3 11.4,46.3 15.087,46.4 49.5,46.4 54.2,46.4 59,46.45 4.4,46.55 39.17,46.65 19.848,47 37.005,47.05 9.469,47.1 13,47.1 44.4,47.1 34.9,47.42 0.8,47.75 32.72,47.85 51.6,48 5.95,48.05 30.568,48.205 61.3,48.5 28.4,48.6 12.345,48.9 9.469,48.95 14.917,48.95 17.294,48.95 26.65,48.95 23.25,49 19.945,49.25 2.65,49.5 4,49.5 34.85,49.5 37.35,49.5 39.85,49.5 42.45,49.5 45,49.5 46.8,49.5 54.7,49.5 10.228,49.55 11.468,49.55 29.75,49.55 32.35,49.55 49.3,49.6 5.95,49.7 21.7,49.95 0.8,50.1 27.6,50.85 57.7,51.3 16.542,51.5 19.1,51.5 23.35,52.05 53.8,52.4 0.8,52.5 6.8,52.5 24.75,52.5 29.85,52.5 35.1,52.5 39.9,52.5 44.7,52.5 49.4,52.5 3.75,52.55
  other v2: 31.05,24.85 32.25,24.85 33.45,24.85 31.05,26.05 32.25,26.05 34.65,26.05 31.05,27.25 33.45,27.25 34.65,27.25 32.25,28.45 33.45,28.45 34.65,28.45
I2C_SCL: I2C.1 J2.10 R2.1 | length 24.8
  Top Layer w0.2: J2.10 2,50.16 2,33.65 ; I2C.1 2,31.15 2,33.65 ; R2.1 2,33.65
I2C_SDA: I2C.2 J2.9 R1.1 | length 34
  Top Layer w0.2: R1.1 4.8,28.95 I2C.2 1.64,29.51 1.64,51.214 2.226,51.8 4.18,51.8 J2.9
MISO: J2.5 R5.6 | length 45
  Top Layer w0.2: J2.5 15.122,50.8 14.072,51.85 12.25,51.85 11.7,51.3 11.7,50.4 13.552,48.548 13.552,22.148 15.88,19.82 15.88,19.32 16.8,18.4 R5.6
MISO_SX: R5.3 U1.18 | length 13.3
  Top Layer w0.2: R5.3 30.35,18.4 32.85,20.9 U1.18
MOSI: J2.4 R5.7 | length 41.1
  Top Layer w0.2: v1(15.1,28) 14.5,28.6 14.5,47.42 J2.4 ; v1(15.122,19.4) 16.622,17.9 R5.7
  MidLayer2 w0.2: v1(15.1,28) 15.1,19.422 v1(15.122,19.4)
MOSI_SX: R5.2 U1.19 | length 14.2
  Top Layer w0.2: R5.2 30.6,17.9 33.5,20.8 U1.19
NetANT_1: ANT.1 C20.2 L6.2 | length 3.9
  Top Layer w0.3: L6.2 C20.2 ANT.1
NetC1_2: C1.2 Q1.1 U1.5 | length 6.6
  Top Layer w0.3: C1.2 C1.2@29.4,33.15 ; Q1.1 30.1,33.15 C1.2@29.4,33.15 ; U1.5 32.2,30.1 31.55,30.75 29.957,30.75 29.4,31.307 C1.2@29.4,33.15
NetC2_2: C2.2 Q1.3 U1.4 | length 3.5
  Top Layer w0.3: Q1.3 32.22,31.925 C2.2 32.245,30.905 32.85,30.3 U1.4
NetC4_2: C4.2 U1.2 | length 1.8
  Top Layer w0.3: U1.2 34.15,30.8 C4.2
NetC5_2: C5.2 U1.3 | length 1.6
  Top Layer w0.3: U1.3 C5.2
NetC7_2: C7.2 C8.2 L1.2 U1.28 | length 5.9
  Top Layer w0.4: U1.28@35.58,28.6 U1.28 36.249,28.6 v1(36.568,28.28) ; v1(36.85,26.5) 37.3,26.95 C7.2 C8.2 L1.2
  MidLayer2 w0.4: v1(36.568,28.28) 36.568,26.782 v1(36.85,26.5)
NetC9_1: C9.1 L3.1 | length 1.1
  Top Layer w0.3: C9.1 L3.1
NetC9_2: C9.2 C10.2 L1.1 U1.24 | length 4.8
  Top Layer w0.3: U1.24 36.25,26 C10.2 C9.2 39.55,25.75 L1.1
NetC11_2: C11.2 C12.2 L3.2 L4.1 | length 3
  Top Layer w0.3: L3.2 C11.2 L4.1 C12.2
NetC12_1: C12.1 C13.2 L4.2 U2.3 | length 4.6
  Top Layer w0.3: C12.1 L4.2 C13.2 ccw(c45.9,26.44) 47.095,25.245 47.85,26 U2.3
NetC14_2: C14.2 L5.1 U1.25 | length 3.3
  Top Layer w0.3: U1.25 36.1,26.65 37.45,28 C14.2 L5.1
NetC15_2: C15.2 L5.2 U4.5 | length 2.5
  Top Layer w0.3: L5.2 C15.2 42.046,28.05 U4.5
NetC16_1: C16.1 U2.1 | length 1.4
  Top Layer w0.3: C16.1 47.746,27.3 U2.1
NetC16_2: C16.2 U4.2 | length 1.7
  Top Layer w0.3: U4.2 C16.2
NetC18_1: C18.1 C19.2 L6.1 | length 5.5
  Top Layer w0.3: C18.1 C19.2 L6.1
NetC18_2: C18.2 U2.5 | length 1.2
  Top Layer w0.3: U2.5 C18.2
NetC22_1: C22.1 R9.1 U2.4 U3.4 | length 10
  Top Layer w0.2: U2.4 C22.1 48.95,23.9 U3.4 48.95,20.2 49.15,20 49.65,20 50.4,19.25 R9.1
NetR7_1: R7.1 R8.1 R9.2 U3.2 | length 3.2
  Top Layer w0.2: R7.1 R8.1 ; U3.2 R8.1 ; R9.2 R8.1
NSS: J2.3 R5.8 | length 42.9
  Top Layer w0.2: v1(15.34,18.14) 15.488,18.14 16.228,17.4 R5.8 ; v1(15.4,28.795) 15.4,28.85 14.9,29.35 14.9,45.28 J2.3
  MidLayer2 w0.2: v1(15.34,18.14) 15.672,18.472 15.672,28.523 v1(15.4,28.795)
NSS_SX: R5.1 U1.20 | length 15.1
  Top Layer w0.2: R5.1 30.85,17.4 34.15,20.7 U1.20
RESET: J4.1 R14.2 | length 51.3
  Top Layer w0.2: v1(14.45,11.05) 15.7,12.3 v1(15.7,15) ; v1(19.35,30.35) 22.35,30.35 R14.2@22.4,30.4
  MidLayer2 w0.2: v1(14.45,11.05) 14.7,10.8 14.7,5.85 16.65,3.9 33.14,3.9 J4.1 ; v1(15.7,15) 16.2,15.5 16.2,27.95 18.6,30.35 v1(19.35,30.35)
RESET_SX: R14.1 U1.6 | length 8.6
  Top Layer w0.2: R14.1 31.3,30.3 31.55,30.05 U1.6
RXTX_EXT: R8.2 R15.1 | length 11.4
  Top Layer w0.2: R15.1 44.65,7.99 v1(44.66,8) ; v1@48.3,15.65 R8.2
  MidLayer2 w0.2: v1(44.66,8) 44.66,13.71 46.5,15.55 v1(48.3,15.55)
RXTX_SX: R7.2 U1.23 | length 16.6
  Top Layer w0.2: U1.23 36.025,25.35 36.55,24.825 v1(36.55,22.55) ; v1(46.6,16.25) R7.2
  MidLayer2 w0.2: v1(36.55,22.55) 36.9,22.2 40.65,22.2 v1(46.6,16.25)
SCK: J2.6 R5.5 | length 39.2
  Top Layer w0.2: J2.6 14,49.6 14,22.377 16.33,20.047 16.33,19.52 16.95,18.9 R5.5
SCK_SX: R5.4 U1.17 | length 12.4
  Top Layer w0.2: R5.4 30.12,18.9 32.2,20.98 U1.17
UART_RX: J1.1 UART.1 | length 57.3
  Top Layer w0.2: v1(8.1,43.7) 8.1,32.55 UART.1 ; v1(23.05,45.05) 23.55,45.55 41.95,45.55 J1.1
  MidLayer2 w0.2: v1(8.1,43.7) 9.45,45.05 v1(23.05,45.05)
UART_TX: J1.2 UART.2 | length 57.7
  Top Layer w0.2: v1(8.4,44.85) 7.55,44 7.55,31.1 UART.2 ; v1(22.35,45.65) 22.65,45.95 39.81,45.95 J1.2
  MidLayer2 w0.2: v1(8.4,44.85) 9.2,45.65 v1(22.35,45.65)
VDD_ANA: ANA_A1.3 ANA_A3.3 C17.2 C25.2 C26.2 C27.2 DIO_D6.3 DIO_D8.3 I2C.3 R1.2 R2.2 R6.1 R10.1 U2.6 U3.5 UART.3 | length 176.2
  Top Layer w0.5: R10.1 v1(46.4,4.05) ; v1(46.65,21.2) C26.2 U3.5@47.6,20.4
  Top Layer w0.6: U2.6@49.95,27.4 C17.2 v1(50.65,28.45)
  Top Layer w0.65: R1.2 R2.2 v1(5.9,34.45)
  Top Layer w0.9: v3(12.1,8.7) C27.2 C25.2 R6.1
  MidLayer2 w0.4: v3(12.1,8.7) 12.1,6.45 15.35,3.2 15.35,2 15.95,1.4 45.3,1.4 45.95,2.05 45.95,3.6 v1(46.4,4.05)
  MidLayer2 w0.6: v1(46.65,21.2) 49.95,24.5 49.95,27.75 v1(50.65,28.45) 50.65,39.45 47.5,42.6
  MidLayer2 w0.8: ANA_A1.3 7.25,12.65 ANA_A3.3 ; I2C.3 7.25,25.65 UART.3 ; DIO_D6.3 6.75,38.65 ; v1(5.9,34.45) 6.7,35.25 6.7,38.6 6.75,38.65 ; DIO_D8.3 6.75,38.65 ; 13.05,38.65 13.1,38.6 13.1,39.55 16.15,42.6 47.5,42.6
  MidLayer2 w1: DIO_D8.3 13.05,38.65 ; v3(12.1,8.7) 11.75,9.05 9.95,9.05 7.25,11.75 7.25,12.65 7.25,25.65 7.25,29.7 13.1,35.55 13.1,38.6
VDD_RF: C23.2 C24.2 J3.4 R3.2 R6.2 VDD_RFS.1 | length 6.3
  Top Layer w0.9: 15.05,7.55 16.55,7.55
  Top Layer w1: 16.9,9.35 17,9.45 R3.2 18.548,9.45 20.248,11.15 VDD_RFS.1 VDD_RFS.1@20.8,11.5
VDD_RFS: C3.2 C6.2 C21.2 R3.1 U1.1 U1.15 VDD_RFS.2 | length 73.9
  Top Layer w0.4: C21.2 30.72,22.57 30.72,23.05 30.9,23.23 U1.15 U1.15@30.9,23.95
  Top Layer w0.5: U1.1@34.8,29.4 U1.1 34.8,30.234 C3.2@35.766,31.2
  Top Layer w0.8: v1(30.7,21.9) C21.2 ; C3.2@35.766,31.2 v1(36.45,31.2)
  Top Layer w1: R3.1 19.3,12.7 21.44,12.7 VDD_RFS.2 v3(26.15,11.15)
  MidLayer2 w0.8: v1(30.7,21.9) 30.7,18.5 29,16.8 29,12.3 27.85,11.15 v3(26.15,11.15) 26.15,13.05 20.7,18.5 20.7,33.202 23.698,36.2 33.75,36.2 37.1,32.85 37.1,31.85 v1(36.45,31.2)
  other v3: 27.1,11.15
pads on no net: J2.8 J3.1 J3.2 J3.3 J3.5 J3.8 J4.6 U1.13 U1.14 U1.21 U1.27 U3.1

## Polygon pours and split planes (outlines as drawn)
GND on Bottom Layer "GND Bottom" (solid, remove dead copper, pour order 8): 0.4,0.4 64.636,0.4 64.7,0.4 64.7,52.9 0.4,52.9
VDD_RF on Top Layer "VDD_RF" (solid, pour order 5): 19.594,1.35 20.4,2.156 20.4,4.8 19.5,5.7 17.6,5.7 17.2,6.1 17.2,9.95 14.85,9.95 14.335,9.45 14.335,2.765 15.75,1.35
GND on Top Layer "GND Top" (solid, remove dead copper, pour order 6): 0.4,0.4 64.7,0.4 64.7,52.9 0.4,52.9
GND on MidLayer1 "GND Midlayer1" (solid, remove dead copper, pour order 7): 0.4,0.4 64.636,0.4 64.7,0.4 64.7,52.9 0.4,52.9

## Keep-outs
Keep-Out Layer:
  the board outline again, w0.05

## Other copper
Top Layer:
  region net GND: 49.4,29 50.6,29 50.6,29.26 49.4,29.26
  pour cut-out: 16.95,10.05 17.1,10.05 17.1,10.4 16.95,10.4
  region net GND: 11.497,7.2 11.497,8.397 11.222,8.397 11.176,8.351 11.176,7.7 11,7.7 11,5.95 11.497,5.95
  region net GND: 49.205,23.795 49.827,24.417 50.46,24.417 50.46,24.112 49.65,24.112 49.65,23.663 49.205,23.663
  pour cut-out: 31.84,23.25 31.78,23.178 31.96,22.998 31.96,23.26
  region net VDD_RFS: 31.1,22.47 30.296,22.47 30.296,23.196 30.74,23.64 31.1,23.64
  region net VDD_RFS: 35.793,31.6 35.26,31.6 35.26,31.018 35.252,31.01 35.462,30.8 35.793,30.8
  region net GND: 41.8,29.57 41.16,29.57 41.16,28.95 41.8,28.95
  region net VDD_RFS: 25.75,11.65 25.75,10.65 27.5,10.65 27.5,11.65
  region net GND: 32.9,31.75 36.15,31.75 36.25,31.85 36.25,32.45 32.9,32.45
  region net GND: 30.262,24.422 30.425,24.422 30.608,24.605 30.82,24.392 30.478,24.05 30.262,24.05
  region net GND: 30.262,28.65 30.262,29.238 30.873,29.238 30.873,28.65
  region net GND: 35.146,29.172 34.817,28.843 34.817,28.795 35.047,28.565 35.489,29.006 35.489,29.014 35.256,29.246
  region net GND: 35.078,24.062 35.078,24.547 35.075,24.55 35.438,24.55 35.438,24.1 35.4,24.062
  pour cut-out: 60.24,27.125 60.579,27.125 60.579,26.175 60.24,26.175
  region net NetANT_1: 60.5,26.8 60.72,27.02 60.753,27.02 60.753,26.28 60.72,26.28 60.5,26.5
  region net GND: 60.38,26.175 56.2,26.175 56.2,25.85 60.38,25.85
  region net GND: 50.776,27.125 50.525,27.125 50.525,27.3
  pour cut-out: 45.425,28.521 45,28.521 45,28.45 45,27.571 45.425,27.571
  pour cut-out: 41.075,28.524 42.584,28.524 42.584,27.575 41.075,27.575
  region net GND: 41.14,28.525 37.01,28.525 36.996,28.7 36.96,28.8 36.9,28.888 36.864,28.93 36.818,28.962 36.891,29.054 37.18,29.054 37.29,28.944 37.29,28.892 41.14,28.892
  region net GND: 43.83,26.97 43.83,26.344 44.484,26.344 44.484,26.97
  region net GND: 45.375,26.252 43.05,26.252 43.05,26.39 45.375,26.39
  region net GND: 36.92,24.275 46.505,24.275 46.83,23.95 36.92,23.95
  region net NetC9_2: 39.88,26.18 39.03,26.18 39.03,25.46 38.65,25.08 38.22,25.08 38.22,24.425 39.17,24.425 39.17,25.14 39.47,25.44 39.88,25.44
  pour cut-out: 29.75,33.9 29.75,30.5 33.05,30.5 33.05,31.75 32.72,31.75 32.72,32.8 30.873,32.8 30.873,33.9
  region net GND: 24.3,8.95 26.1,8.95 26.1,9.25 24.3,9.25
  region net GND: 19.3,5.853 17.747,5.853 17.457,6.143 17.457,8.622 17.635,8.8 18.797,8.8 18.837,8.868 19.3,8.868 19.286,8.853 19.286,8.5 18.1,8.5 18.1,6.25 19.3,6.25
  region net GND: 17.768,7.6 19.518,7.6 19.518,7.2 17.768,7.2
  region net GND: 37.18,26.18 37.18,25.522 37.472,25.23 38.58,25.23 38.87,25.52 38.87,26.18
  region net GND: 37.05,28.525 37.046,28.525 36.975,28.525 36.879,28.613 36.818,28.656 36.74,28.709 36.7,28.727 36.62,28.727 36.62,28.95 36.632,28.962 37.041,28.962 37.05,28.953
  region net GND: 29.85,31.775 29.85,31.282 30.069,31.062 30.362,31.062 30.6,31.3 30.6,31.775
  region net GND: 29.85,33.9 29.7,33.9 29.7,33.75 28.75,33.75 28.75,34 29.85,34
  pour cut-out: 46.35,25.225 46.568,25.225 46.7,25.225 46.678,25.203 cw(c46.43,25.451) 46.43,25.1
MidLayer2:
  region net VDD_RFS: 25.75,11.65 25.75,10.65 27.5,10.65 27.5,11.65
Bottom Layer:
  region net GND: 30.625,28.85 30.625,24.4 35.075,24.4 35.075,28.85

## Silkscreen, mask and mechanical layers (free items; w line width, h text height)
Top Overlay:
  text "1" at 48.75,50.3 h1
  text "1" at 27,50.26 h1
  text "Sensors" at 2.7,47.65 h1.4
  text "J2" at 24.5,47.6 h1.27
  text "J1" at 46.4,47.6 h1.27
  text "SX1272 mbed shield" at 24.85,44.3 h1.4
  text "D6" at 6.65,43.498 h0.8 r270
  text "D8" at 14.2,43.498 h0.8 r270
  text "D7" at 6.65,41.398 h0.8 r270
  text "D9" at 14.2,41.398 h0.8 r270
  text "SX1272MB2xAS" at 28.65,41.35 h1.4
  text "SCL" at 6.65,31.198 h0.8 r270
  text "RX" at 14.2,30.548 h0.8 r270
  text "1" at 36.323,29.25 h0.8
  text "SDA" at 6.65,28.598 h0.8 r270
  text "TX" at 14.2,28.481 h0.8 r270
  text "SX1272" at 28.98,20.3 h1.4
  text "A3" at 14.2,17.448 h0.8 r270
  text "A1" at 6.65,17.398 h0.8 r270
  text "A2" at 6.65,15.398 h0.8 r270
  text "A4" at 14.2,15.348 h0.8 r270
  text "J3" at 10.49,4.5 h1.27
  text "J4" at 33.4,4.5 h1.27
  text "1" at 32.476,2.1 h1
  text "1" at 9.53,2.05 h1
Bottom Overlay:
  text "RoHS" at 31,39.9 h2.2 r270
  text "compliant" at 29.45,37.85 h2.2 r270
  text "PCB_E364V02A  0916" at 1.05,18.1 h1 r270
Top Solder:
  region: 64.25,30.4 64.75,30.4 64.75,28.1 64.25,28.1
  region: 64.15,25.2 64.75,25.2 64.75,22.9 64.15,22.9
Bottom Solder:
  region: 64.25,30.4 64.75,30.4 64.75,28.1 64.25,28.1
  region: 64.15,25.2 64.75,25.2 64.75,22.9 64.15,22.9
Mechanical 3:
  lines w0.05: 0,8.65 0,44.65 ; 53.6,3.3 55.402,3.3 ; 54.5,2.4 54.5,4.2
  text "Origin(0;0)" at -10.1,-1.6 h1
Mechanical 14:
  the board outline again, w0.05
Mechanical 15:
  lines w0.05: 0,26.65 65,26.65

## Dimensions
52.3,40.6 to 68,52.5 on Mechanical 3
0,0 to 54.5,3.3 on Mechanical 3
0,0 to 54.5,3.3 on Mechanical 3
0,0 to 0,53.3 on Mechanical 3
0,0 to 65,12.7 on Mechanical 3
